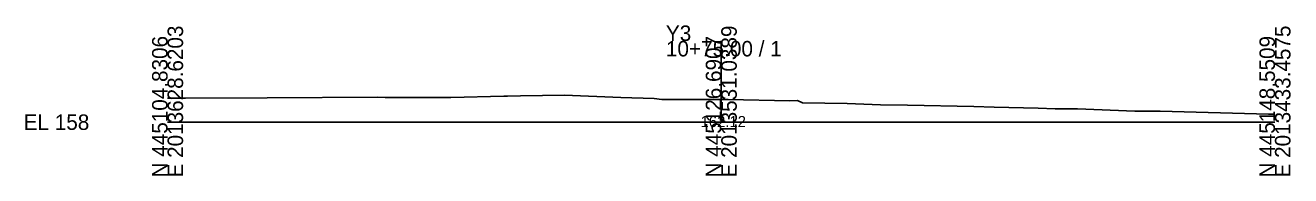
# Model space of a CAD drawing. Extents: x -26 to 203, y -10 to 5017.
# Drawn here: x -25.7 to 202.8, y 1490.3 to 1517.5 of the extents above; entities that cross this region are included whole.
import ezdxf

# ---------------------------------------------------------------- set-up
doc = ezdxf.new("R2010")
doc.units = 0
for name, color, linetype in [('Default', 7, 'Continuous'), ('Exist Cross Section Cell', 7, 'Continuous'), ('Exist XS Center Line Elevation Label', 7, 'Continuous'), ('Exist XS Ground Line', 7, 'Continuous')]:
    doc.layers.add(name, color=color, linetype=linetype)

msp = doc.modelspace()

# ---------------------------------------------------------------- linework, layer by layer
at = {"layer": 'Exist Cross Section Cell'}
for p, q in [((100, 1500), (100, 1514.7)), ((0, 1500), (100, 1500)), ((100, 1500), (200, 1500))]:
    msp.add_line(p, q, dxfattribs=at)
at = {"layer": 'Exist XS Ground Line'}
msp.add_lwpolyline([(0, 1504.32), (1.74, 1504.32), (3.22, 1504.35), (18, 1504.42), (37.93, 1504.5), (39.32, 1504.48), (47.53, 1504.49), (51.16, 1504.49), (60.73, 1504.69), (61.41, 1504.7), (63.75, 1504.76), (71.66, 1504.9), (81.89, 1504.45), (87.89, 1504.27), (89.29, 1504.11), (99.69, 1504.12), (100, 1504.12), (100.37, 1504.12), (101.23, 1504.1), (112.4, 1503.85), (113.78, 1503.91), (114.69, 1503.53), (122.76, 1503.38), (128.78, 1503.17), (133.65, 1503.1), (145.63, 1502.82), (149.31, 1502.72), (157.23, 1502.51), (160.3, 1502.42), (162.26, 1502.42), (162.98, 1502.4), (163.73, 1502.39), (164.34, 1502.39), (174.67, 1502.02), (179.29, 1501.98), (198.81, 1501.47), (199.15, 1501.46), (200, 1501.43)], dxfattribs=at)

# ---------------------------------------------------------------- texts
at = {"layer": 'Default'}
msp.add_text('-', height=0.0001, dxfattribs=at).set_placement((0, 1500))
at = {"layer": 'Exist Cross Section Cell'}
for s, p in [('Y3', (90, 1514.7)), ('10+75.00 / 1', (90, 1511.9)), ('EL 158', (-26, 1498.6))]:
    msp.add_text(s, height=2.8, dxfattribs=at).set_placement(p)
for s, p in [('N 445104.8306', (0, 1490)), ('E 2013628.6203', (2.8, 1490)), ('N 445126.6907', (100, 1490)), ('E 2013531.0389', (102.8, 1490)), ('N 445148.5509', (200, 1490)), ('E 2013433.4575', (202.8, 1490))]:
    msp.add_text(s, height=2.8, rotation=90, dxfattribs=at).set_placement(p)
at = {"layer": 'Exist XS Center Line Elevation Label'}
msp.add_text('162.12', height=2, dxfattribs=at).set_placement((96.27, 1499.12))

doc.saveas('drawing.dxf')
